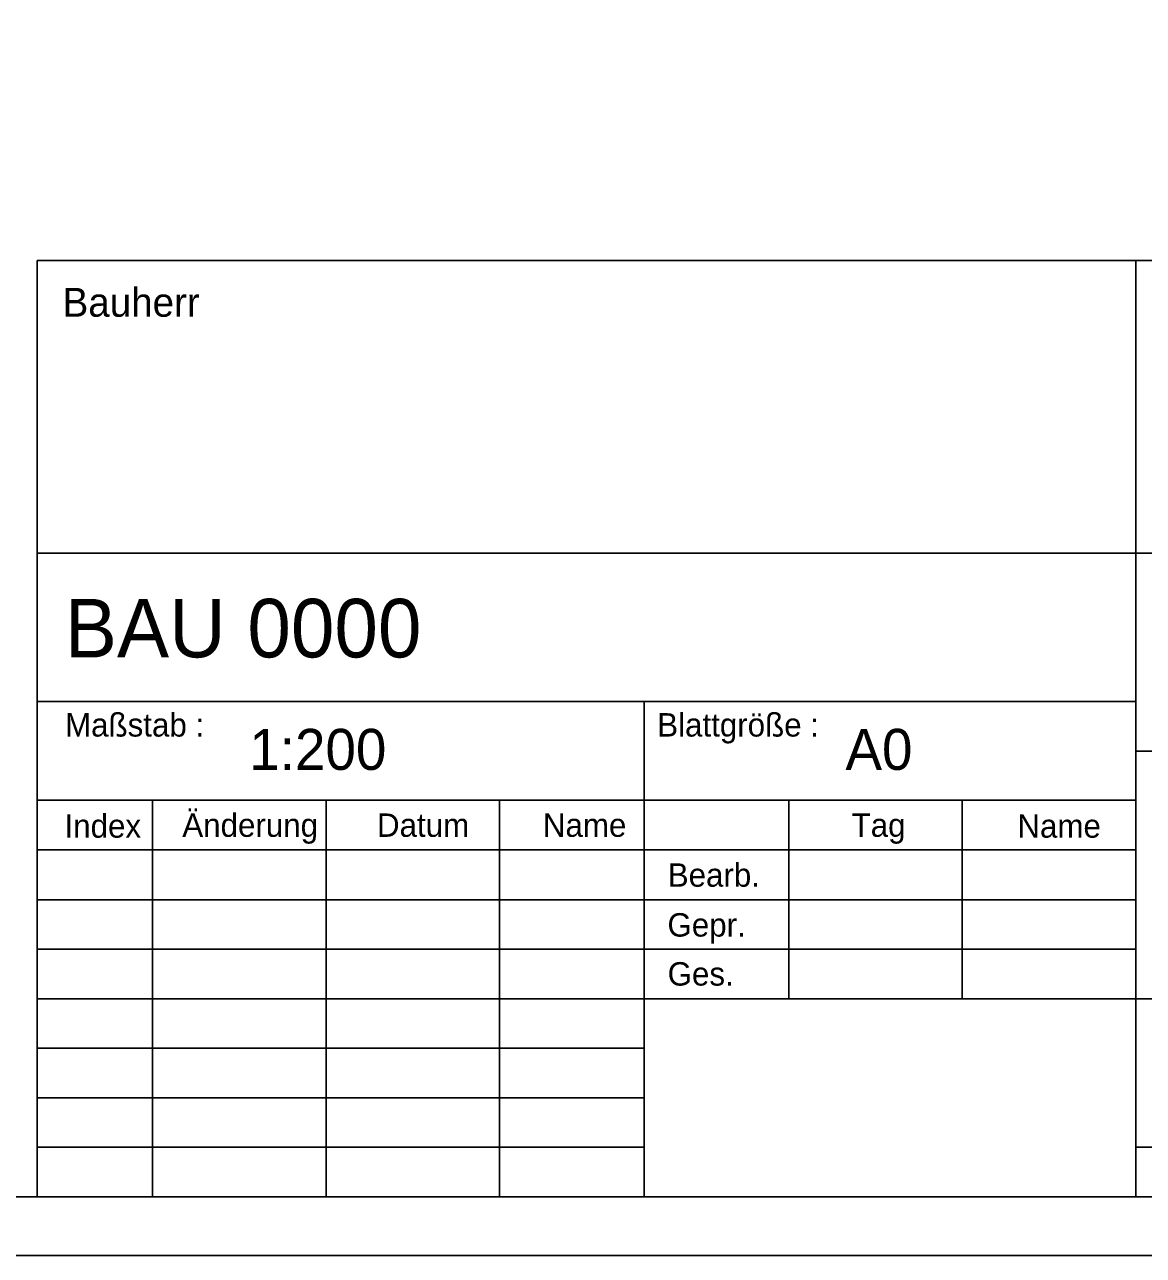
# Model space of a CAD drawing. Extents: x 0 to 238, y 0 to 168.
# Drawn here: x 201.01 to 220.13, y 0 to 21.03 of the extents above; entities that cross this region are included whole.
import ezdxf

# ---------------------------------------------------------------- set-up
doc = ezdxf.new("R2010")
doc.units = 0
doc.layers.add('90_Plankopf', color=7, linetype='Continuous')

msp = doc.modelspace()

# ---------------------------------------------------------------- linework, layer by layer
at = {"layer": '90_Plankopf'}
for p, q in [((236.8, 16.998), (201.224, 16.998)), ((201.224, 16.998), (201.224, 11.998)), ((220, 11.998), (220, 16.998)), ((201.224, 11.998), (236.8, 11.998)), ((201.224, 1), (201.224, 11.998)), ((201.224, 11.998), (236.8, 11.998)), ((220, 1), (220, 11.998)), ((201.224, 9.46), (220, 9.46)), ((211.6, 1), (211.6, 9.46)), ((220, 8.614), (236.8, 8.614)), ((201.224, 7.774), (220, 7.774)), ((203.2, 7.768), (203.2, 1)), ((206.165, 1), (206.165, 7.768)), ((209.13, 1), (209.13, 7.768)), ((214.071, 7.768), (214.071, 4.384)), ((217.036, 4.384), (217.036, 7.768)), ((201.224, 6.926), (220, 6.926)), ((201.224, 6.076), (220, 6.076)), ((201.224, 5.23), (220, 5.23)), ((201.224, 4.384), (220, 4.384)), ((201.224, 4.384), (220, 4.384)), ((211.6, 4.384), (220, 4.384)), ((220, 4.384), (236.8, 4.384)), ((211.6, 3.538), (201.224, 3.538)), ((211.6, 2.692), (201.224, 2.692)), ((201.224, 1.846), (211.6, 1.846)), ((220, 1.846), (236.8, 1.846)), ((236.8, 1), (201.224, 1)), ((201.224, 1), (211.6, 1)), ((203.56, 1), (236.8, 1)), ((203.56, 1), (236.8, 1))]:
    msp.add_line(p, q, dxfattribs=at)
for points in [[(0, 0), (237.8, 0), (237.8, 168.2), (0, 168.2)], [(5, 1), (236.8, 1), (236.8, 167.2), (5, 167.2)]]:
    msp.add_lwpolyline(points, close=True, dxfattribs=at)

# ---------------------------------------------------------------- texts
for s, height, p in [('Bauherr', 0.4927, (201.661, 16.035)), ('BAU 0000      ', 1, (201.698, 10.215)), ('Maßstab :', 0.4, (201.703, 8.863)), ('Blattgröße :', 0.39998, (211.823, 8.863)), ('1:200    ', 0.7, (204.852, 8.294)), ('A0       ', 0.7, (215.04, 8.294)), ('Änderung', 0.4, (203.707, 7.15)), ('Index', 0.4, (201.694, 7.135)), ('Datum', 0.4, (207.034, 7.15)), ('Name', 0.4, (209.869, 7.15)), ('Tag', 0.4, (215.145, 7.15)), ('Name', 0.4, (217.978, 7.135)), ('Bearb.', 0.4, (212.003, 6.298)), ('Gepr.', 0.4, (211.998, 5.446)), ('Ges.', 0.4, (212.001, 4.609))]:
    msp.add_text(s, height=height, dxfattribs=at).set_placement(p)

doc.saveas('drawing.dxf')
